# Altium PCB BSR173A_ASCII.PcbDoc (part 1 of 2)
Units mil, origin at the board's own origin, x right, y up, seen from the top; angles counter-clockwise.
Board outline 3000 x 1500 mil, 4 copper layers (Top Layer, Signal Layer 1, Signal Layer 2, Bottom Layer), stack 61.2 mil thick; 64 components, 17 nets, 119 pads, 82 vias.
Unrouted connection lines stored in the file: 2.
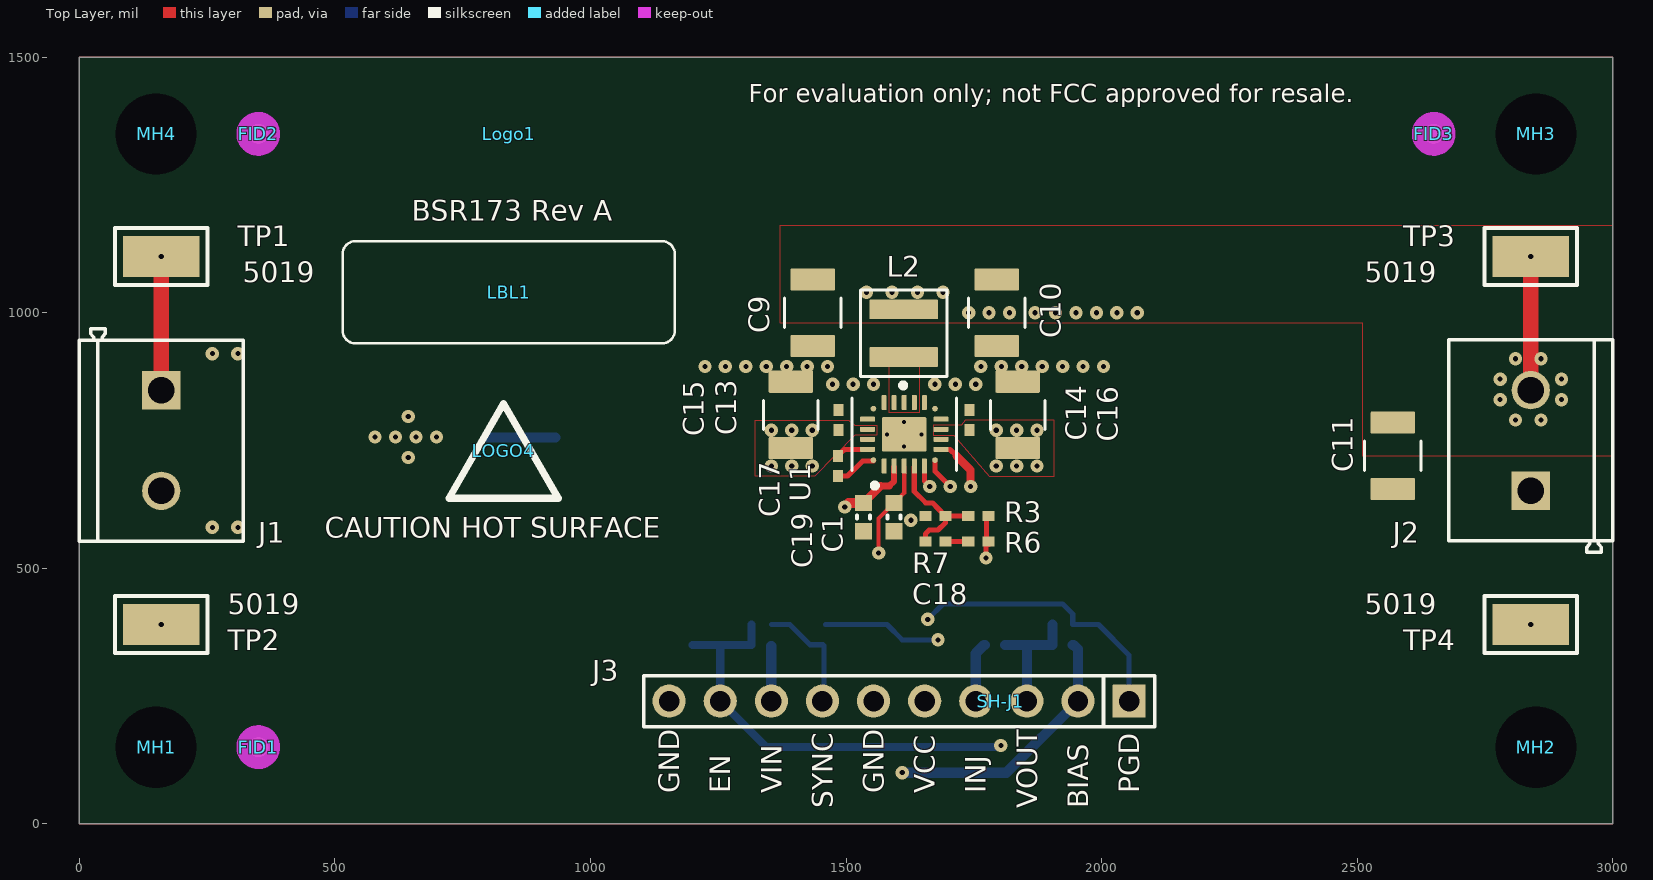
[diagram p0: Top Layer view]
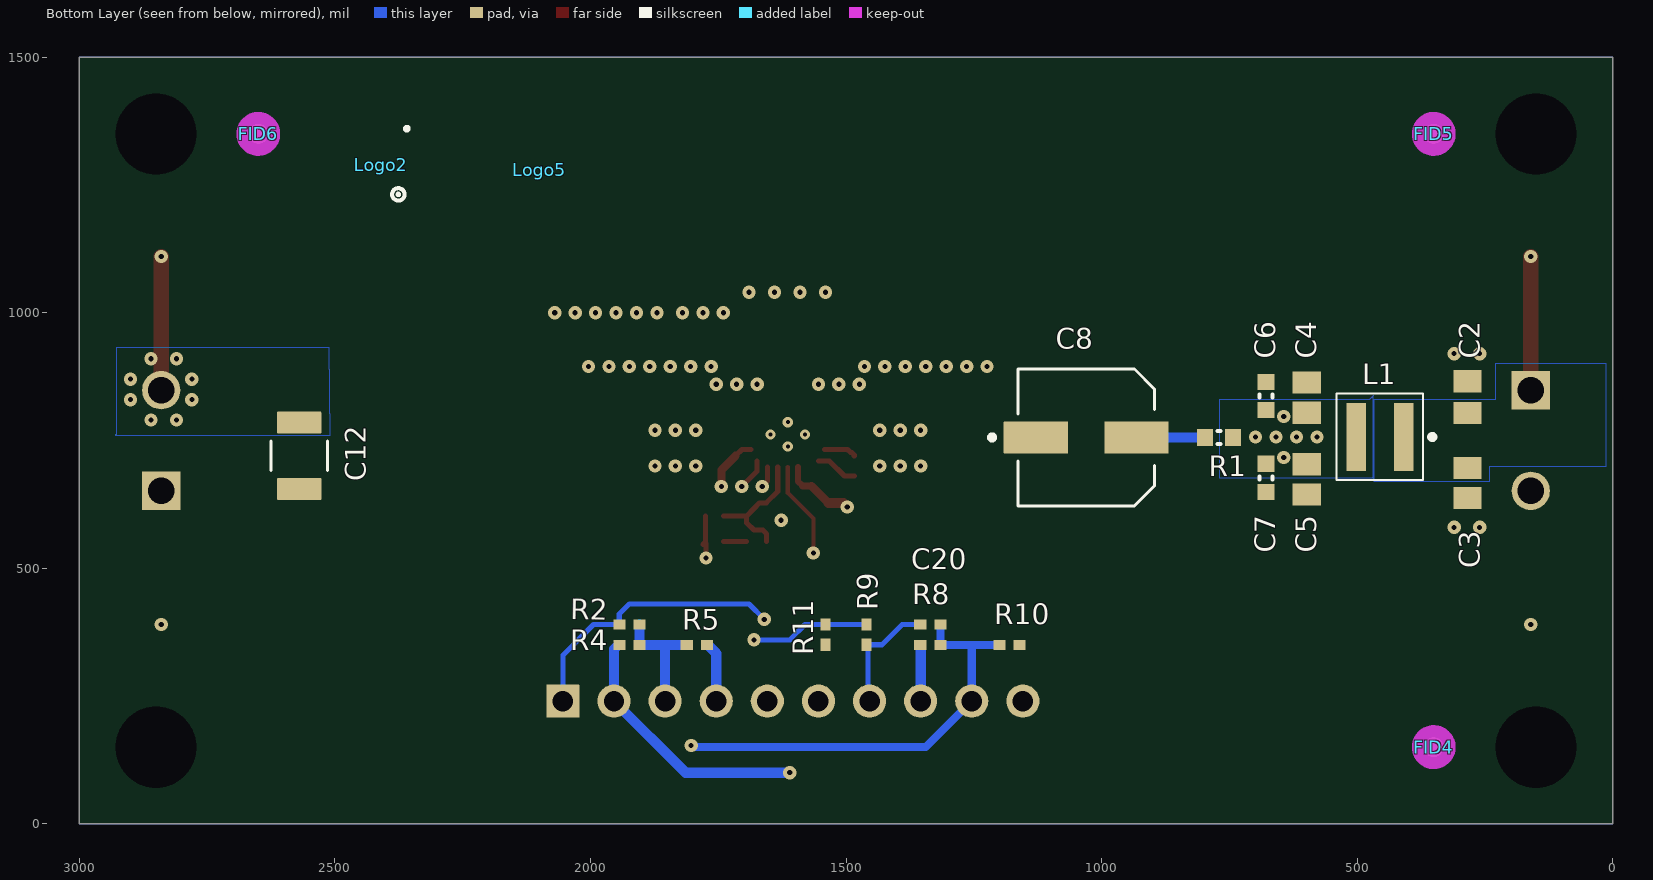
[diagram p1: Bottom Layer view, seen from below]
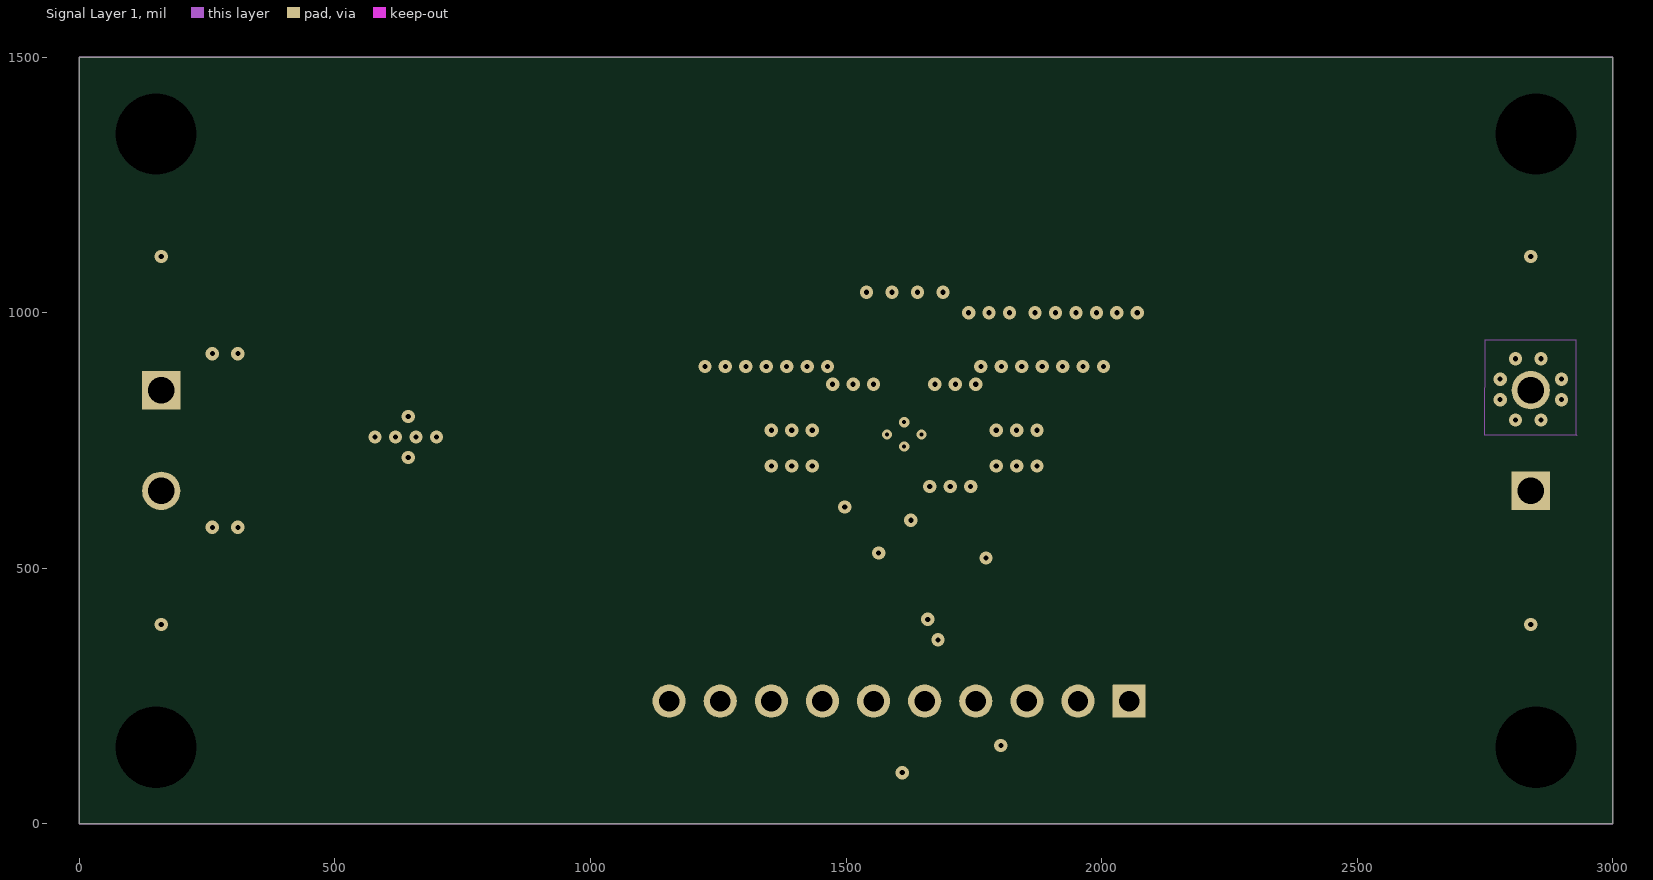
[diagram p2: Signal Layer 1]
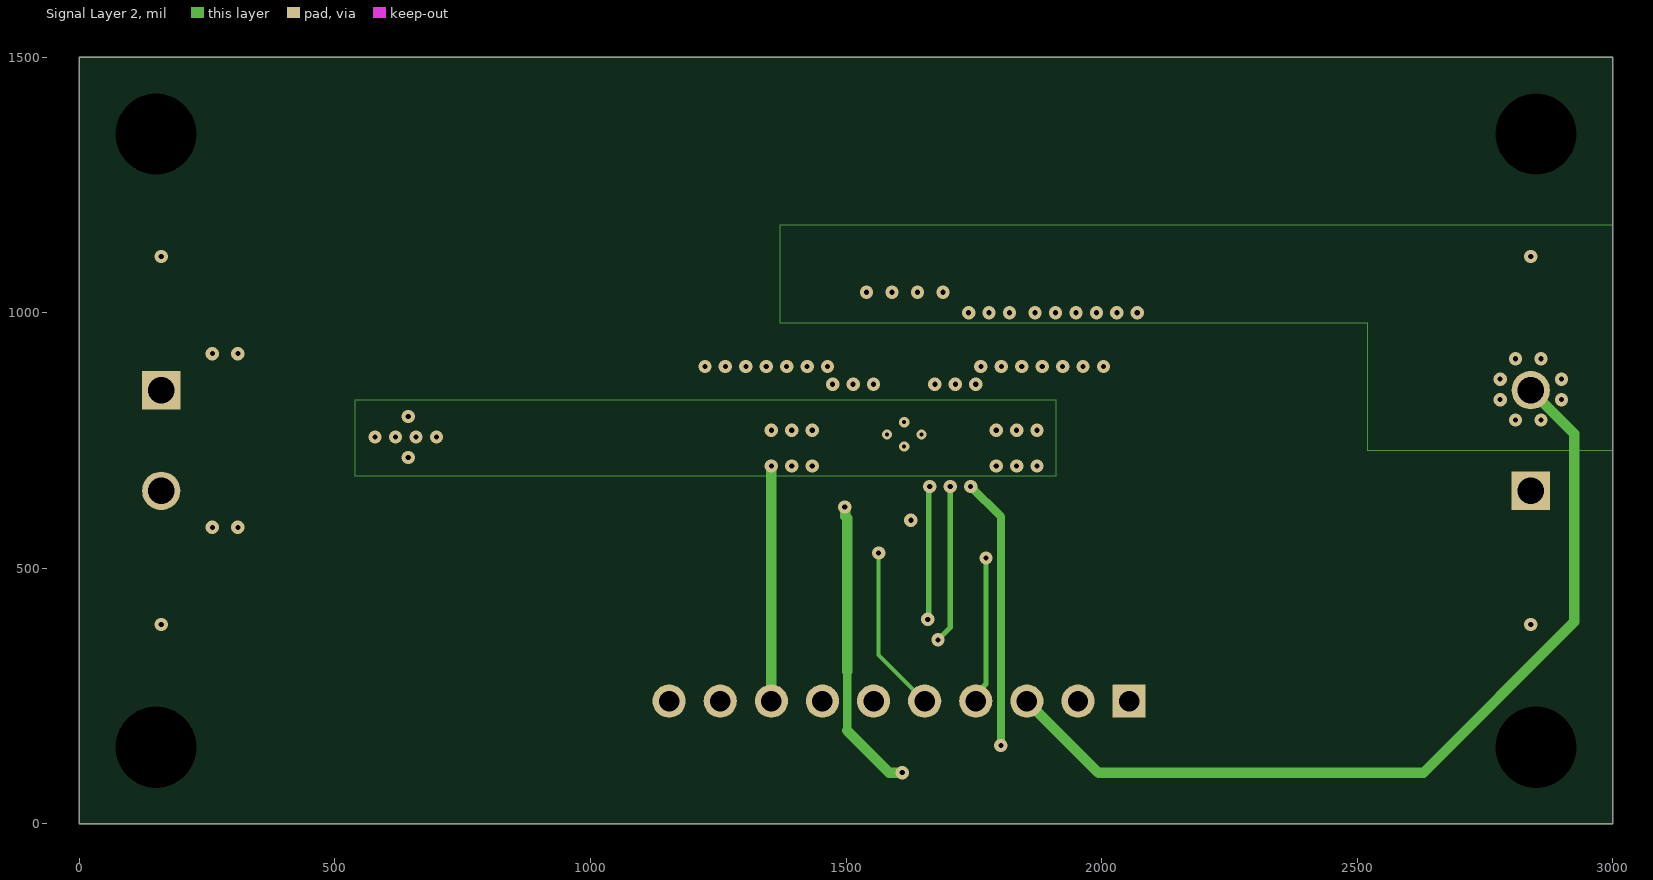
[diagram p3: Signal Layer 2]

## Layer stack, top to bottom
Top Solder: solder mask 0.4, Solder Resist, Dk 3.5
Top Layer: signal copper 2.8
Dielectric 1: prepreg 5, FR-4 High Tg, Dk 4.2
Signal Layer 1: signal copper 2.8
Dielectric 2: core 40, FR-4 High Tg, Dk 4.2
Signal Layer 2: signal copper 2.8
Dielectric 3: prepreg 5, FR-4 High Tg, Dk 4.2
Bottom Layer: signal copper 2.8
Bottom Solder: solder mask 0.4, Solder Resist, Dk 3.5

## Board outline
0,0 0,1500 3000,1500 3000,0

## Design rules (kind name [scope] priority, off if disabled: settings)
AcuteAngle [All] p0: scope1count=1 scope1_0_kind=Board scope1_0_value=Board scope2count=1 scope2_0_kind=Board scope2_0_value=Board commentlength=0 minimum=4.50000000000000E+0001
AcuteAngle [All] p1: minimum=4.50000000000000E+0001 checktracksonly=FALSE
AssemblyTestPointUsage [All] p0: scope1count=1 scope1_0_kind=Board scope1_0_value=Board scope2count=1 scope2_0_kind=Board scope2_0_value=Board commentlength=0
AssemblyTestPointUsage [All] p1: valid=2
AssemblyTestpoint [All] p0: scope1count=1 scope1_0_kind=Board scope1_0_value=Board scope2count=1 scope2_0_kind=Board scope2_0_value=Board commentlength=0
BoardOutlineClearance BoardOutlineClearance_MountingHoles [All] p0 off: scope1count=1 scope1_0_kind=Board scope1_0_value=Board scope2count=1 scope2_0_kind=Board scope2_0_value=Board commentlength=86 gap=40 // Protel DXP Scope 1 Expression Was: OnCopper and InComponentClass('Mounting Holes')
BoardOutlineClearance BoardOutlineClearance_Poly [All] p0 off: scope1count=1 scope1_0_kind=Board scope1_0_value=Board scope2count=1 scope2_0_kind=Board scope2_0_value=Board commentlength=58 gap=25 // Protel DXP Scope 1 Expression Was: OnCopper and IsPoly
BoardOutlineClearance [All] p0 off: scope1count=1 scope1_0_kind=Board scope1_0_value=Board scope2count=1 scope2_0_kind=Board scope2_0_value=Board commentlength=172 gap=65 // Protel DXP Scope 1 Expression Was: OnCopper and Not InComponentClass('Logo') and not InComponentClass('FiducialMark') and not InRegion(1000,500,4000,800) and not InPoly
BoardOutlineClearance BoardOutlineClearance_1 [All] p0: scope1count=1 scope1_0_kind=Footprint scope1_0_value=Edge_Connector_EDAC_12x2 scope2count=1 scope2_0_kind=Board scope2_0_value=Board commentlength=0 gap=0
BoardOutlineClearance BoardOutlineClearance_1 [HasFootprint('Edge_Connector_EDAC_12x2')] p1: gap=0 ignorepadtopadclearanceinfootprint=FALSE
BoardOutlineClearance BoardOutlineClearance_MountingHoles [OnCopper and InComponentClass('Mounting Holes')] p2: gap=40 ignorepadtopadclearanceinfootprint=FALSE
BoardOutlineClearance BoardOutlineClearance_Poly [OnCopper and IsPoly] p3: gap=25 ignorepadtopadclearanceinfootprint=FALSE
BoardOutlineClearance [OnCopper and Not InComponentClass('Logo') and not InComponentClass('FiducialMark') and not InRegion(1000,500,4000,800) and not InPoly] p4: gap=65 ignorepadtopadclearanceinfootprint=FALSE
Clearance "Stitching VIN_PIN" [All] p0 off: scope1count=1 scope1_0_kind=Board scope1_0_value=Board scope2count=1 scope2_0_kind=Board scope2_0_value=Board commentlength=80 gap=9 // Protel DXP Scope 2 Expression Was: (IsVia and (Not IsStitchingVia)) Or IsPad
Clearance Clearance_Keepouts [All] p0 off: scope1count=1 scope1_0_kind=Board scope1_0_value=Board scope2count=1 scope2_0_kind=Board scope2_0_value=Board commentlength=99 gap=0 // Protel DXP Scope 2 Expression Was: ((IsTrack Or IsArc) And Not InPoly) And IsFree and IsKeepOut
Clearance Clearance_Poly [All] p0 off: scope1count=1 scope1_0_kind=Board scope1_0_value=Board scope2count=1 scope2_0_kind=Board scope2_0_value=Board commentlength=48 gap=10 // Protel DXP Scope 1 Expression Was: InPolygon
Clearance Clearance_FiducialMark [All] p0 off: scope1count=1 scope1_0_kind=Board scope1_0_value=Board scope2count=1 scope2_0_kind=Board scope2_0_value=Board commentlength=81 gap=0 // Protel DXP Scope 2 Expression Was: IsPad and InComponentClass('FiducialMark')
Clearance [All] p0: scope1count=1 scope1_0_kind=Board scope1_0_value=Board scope2count=1 scope2_0_kind=Board scope2_0_value=Board commentlength=0 gap=7.87
Clearance "Stitching VIN_PIN" [IsStitchingVia and InNet('VIN_PIN') vs (IsVia and (Not IsStitchingVia)) Or IsPad] p1: gap=9 ignorepadtopadclearanceinfootprint=FALSE
Clearance Clearance_Keepouts [((IsTrack Or IsArc) And Not InPoly) And IsFree and IsKeepOut vs ((IsTrack Or IsArc) And Not InPoly) And IsFree and IsKeepOut] p2: gap=0 ignorepadtopadclearanceinfootprint=FALSE
Clearance Clearance_Poly [InPolygon] p3: gap=10 ignorepadtopadclearanceinfootprint=FALSE
Clearance Clearance_FiducialMark [IsKeepOut and InComponentClass('FiducialMark') vs IsPad and InComponentClass('FiducialMark')] p4: gap=0 ignorepadtopadclearanceinfootprint=FALSE
Clearance [All] p5: gap=7.87 ignorepadtopadclearanceinfootprint=FALSE except(0: Arc-Hole Track-Hole SMDPad-Hole THPad-Hole Via-Hole Fill-Hole Poly-Hole Region-Hole Text-Hole)
ComponentClearance ComponentClearance_MountingHoles_FiducialMarks [All] p0: scope1count=1 scope1_0_kind=ComponentClass scope1_0_value="Mounting Holes" scope2count=1 scope2_0_kind=ComponentClass scope2_0_value=FiducialMark commentlength=0 gap=50 collisioncheckmode=3
ComponentClearance ComponentClearance_Shunt [All] p0: scope1count=1 scope1_0_kind=ComponentClass scope1_0_value=Header scope2count=1 scope2_0_kind=ComponentClass scope2_0_value=Shunt commentlength=0 gap=0 collisioncheckmode=3
ComponentClearance ComponentClearance_Logo [All] p0: scope1count=1 scope1_0_kind=ComponentClass scope1_0_value=Logo scope2count=1 scope2_0_kind=Board scope2_0_value=Board commentlength=0 gap=50 collisioncheckmode=3
ComponentClearance ComponentClearance_ScrewToNut [All] p0 off: scope1count=1 scope1_0_kind=Board scope1_0_value=Board scope2count=1 scope2_0_kind=Board scope2_0_value=Board commentlength=71 gap=5 collisioncheckmode=3 // Protel DXP Scope 2 Expression Was: (HasFootprint('Keystone_1902C'))
ComponentClearance ComponentClearance_MountingHoles [All] p0: scope1count=1 scope1_0_kind=ComponentClass scope1_0_value="Mounting Holes" scope2count=1 scope2_0_kind=Board scope2_0_value=Board commentlength=0 gap=0 collisioncheckmode=3
ComponentClearance ComponentClearance_SmallPassives [All] p0 off: scope1count=1 scope1_0_kind=Board scope1_0_value=Board scope2count=1 scope2_0_kind=Board scope2_0_value=Board commentlength=508 gap=14.96 collisioncheckmode=3 // Protel DXP Scope 2 Expression Was: HasFootprint('0201*') or HasFootprint('0402*') or HasFootprint('0508') or HasFootprint('0603*') or HasFootprint('0612') or HasFootprint('0805*') or HasFootprint('0815*') or HasFootprint('0830*') or HasFootprint('1206*') or HasFootprint('1210*') or HasFootprint('1808*') or HasFootprint('1812*') or HasFootprint('1825*') or HasFootprint('2010*') or HasFootprint('2220*') or HasFootprint('2225*') or HasFootprint('2512*') or HasFootprint('2728*') or HasFootprint('3518*')
ComponentClearance ComponentClearance_THtoSMT [All] p0 off: scope1count=1 scope1_0_kind=Board scope1_0_value=Board scope2count=1 scope2_0_kind=Board scope2_0_value=Board commentlength=53 gap=40 collisioncheckmode=3 // Protel DXP Scope 2 Expression Was: IsSMTComponent
ComponentClearance ComponentClearance_THtoTH [All] p0 off: scope1count=1 scope1_0_kind=Board scope1_0_value=Board scope2count=1 scope2_0_kind=Board scope2_0_value=Board commentlength=54 gap=30 collisioncheckmode=3 // Protel DXP Scope 2 Expression Was: IsThruComponent
ComponentClearance [All] p0: scope1count=1 scope1_0_kind=Board scope1_0_value=Board scope2count=1 scope2_0_kind=Board scope2_0_value=Board commentlength=0 gap=30 collisioncheckmode=3
ComponentClearance ComponentClearance_MountingHoles_FiducialMarks [InComponentClass('Mounting Holes') vs InComponentClass('FiducialMark')] p1: gap=50 collisioncheckmode=3 verticalgap=10 showdistances=FALSE
ComponentClearance ComponentClearance_Shunt [InComponentClass('Header') vs InComponentClass('Shunt')] p2: gap=0 collisioncheckmode=3 verticalgap=0 showdistances=FALSE
ComponentClearance ComponentClearance_Logo [InComponentClass('Logo')] p3: gap=50 collisioncheckmode=3 verticalgap=10 showdistances=FALSE
ComponentClearance ComponentClearance_ScrewToNut [(HasFootprint('NY PMS 440 0025 PH')) vs (HasFootprint('Keystone_1902C'))] p4: gap=5 collisioncheckmode=3 verticalgap=10 showdistances=FALSE
ComponentClearance ComponentClearance_MountingHoles [InComponentClass('Mounting Holes')] p5: gap=0 collisioncheckmode=3 verticalgap=100000 showdistances=FALSE
ComponentClearance ComponentClearance_SmallPassives [HasFootprint('0201*') or HasFootprint('0402*') or HasFootprint('0508') or HasFootprint('0603*') or HasFootprint('0612') or HasFootprint('0805*') or HasFootprint('0815*') or HasFootprint('0830*') or HasFootprint('1206*') or HasFootprint('1210*') or HasFootprint('1808*') or HasFootprint('1812*') or HasFootprint('1825*') or HasFootprint('2010*') or HasFootprint('2220*') or HasFootprint('2225*') or HasFootprint('2512*') or HasFootprint('2728*') or HasFootprint('3518*') vs HasFootprint('0201*') or HasFootprint('0402*') or HasFootprint('0508') or HasFootprint('0603*') or HasFootprint('0612') or HasFootprint('0805*') or HasFootprint('0815*') or HasFootprint('0830*') or HasFootprint('1206*') or HasFootprint('1210*') or HasFootprint('1808*') or HasFootprint('1812*') or HasFootprint('1825*') or HasFootprint('2010*') or HasFootprint('2220*') or HasFootprint('2225*') or HasFootprint('2512*') or HasFootprint('2728*') or HasFootprint('3518*')] p6: gap=14.96 collisioncheckmode=3 verticalgap=10 showdistances=FALSE
ComponentClearance ComponentClearance_THtoSMT [IsThruComponent vs IsSMTComponent] p7: gap=40 collisioncheckmode=3 verticalgap=30 showdistances=FALSE
ComponentClearance ComponentClearance_THtoTH [IsThruComponent vs IsThruComponent] p8: gap=30 collisioncheckmode=3 verticalgap=30 showdistances=FALSE
ComponentClearance [All] p9: gap=30 collisioncheckmode=3 verticalgap=10 showdistances=FALSE
DiffPairsRouting [All] p0: scope1count=1 scope1_0_kind=Board scope1_0_value=Board scope2count=1 scope2_0_kind=Board scope2_0_value=Board commentlength=0
DiffPairsRouting [All] p1: maxlimit=100 minlimit=10 mostfreqgap=10 toplayer_minwidth=15 toplayer_maxwidth=15 toplayer_prefwidth=15 midlayer1_minwidth=15 midlayer1_maxwidth=15 midlayer1_prefwidth=15 midlayer2_minwidth=15 midlayer2_maxwidth=15 midlayer2_prefwidth=15 bottomlayer_minwidth=15 bottomlayer_maxwidth=15 bottomlayer_prefwidth=15 maxuncoupledlength=1000
FabricationTestPointUsage TestPointUsage [All] p0: scope1count=1 scope1_0_kind=Board scope1_0_value=Board scope2count=1 scope2_0_kind=Board scope2_0_value=Board commentlength=0 valid=2 allowmultiple=FALSE
FabricationTestPointUsage TestPointUsage [All] p1: valid=2 allowmultiple=FALSE
FabricationTestpoint Testpoint [All] p0: scope1count=1 scope1_0_kind=Board scope1_0_value=Board scope2count=1 scope2_0_kind=Board scope2_0_value=Board commentlength=0 side=3 testpointundercomponent=TRUE minsize=40 maxsize=100 preferedsize=60 minholesize=0 maxholesize=40 preferedholesize=32 testpointgrid=1
FabricationTestpoint Testpoint [All] p1: side=3 testpointundercomponent=TRUE minsize=40 maxsize=100 preferedsize=60 minholesize=0 maxholesize=40 preferedholesize=32 testpointgrid=1 allowsidetop=TRUE allowsidebottom=TRUE usegrid=TRUE gridtolerance=0.01
FanoutControl Fanout_LCC [All] p0 off: scope1count=1 scope1_0_kind=Board scope1_0_value=Board scope2count=1 scope2_0_kind=Board scope2_0_value=Board commentlength=69 // Protel DXP Scope 1 Expression Was: IsLCC   Fanout_LCC (Default Rule)
FanoutControl Fanout_BGA [All] p0 off: scope1count=1 scope1_0_kind=Board scope1_0_value=Board scope2count=1 scope2_0_kind=Board scope2_0_value=Board commentlength=69 // Protel DXP Scope 1 Expression Was: IsBGA   Fanout_BGA (Default Rule)
FanoutControl Fanout_SOIC [All] p0 off: scope1count=1 scope1_0_kind=Board scope1_0_value=Board scope2count=1 scope2_0_kind=Board scope2_0_value=Board commentlength=71 // Protel DXP Scope 1 Expression Was: IsSOIC   Fanout_SOIC (Default Rule)
FanoutControl Fanout_Default [All] p0: scope1count=1 scope1_0_kind=Board scope1_0_value=Board scope2count=1 scope2_0_kind=Board scope2_0_value=Board commentlength=30 // Fanout_Default (Default Rule)
FanoutControl Fanout_Small [All] p0 off: scope1count=1 scope1_0_kind=Board scope1_0_value=Board scope2count=1 scope2_0_kind=Board scope2_0_value=Board commentlength=84 // Protel DXP Scope 1 Expression Was: (CompPinCount < 5)   Fanout_Small (Default Rule)
FanoutControl Fanout_LCC [IsLCC] p1: bgadir=Out bgaviamode=Centered fanoutstyle=Auto fanoutdirection=Alternating viagrid=1 // Fanout_LCC (Default Rule)
FanoutControl Fanout_BGA [IsBGA] p2: bgadir=Out bgaviamode=Centered fanoutstyle=Auto fanoutdirection=Alternating viagrid=1 // Fanout_BGA (Default Rule)
FanoutControl Fanout_Default [All] p4: bgadir=Out bgaviamode=Centered fanoutstyle=Auto fanoutdirection=Alternating viagrid=1 // Fanout_Default (Default Rule)
FanoutControl Fanout_Small [(CompPinCount < 5)] p5: bgadir=Out bgaviamode=Centered fanoutstyle=Auto fanoutdirection=OutThenIn viagrid=1 // Fanout_Small (Default Rule)
Height [All] p0: scope1count=1 scope1_0_kind=Board scope1_0_value=Board scope2count=1 scope2_0_kind=Board scope2_0_value=Board commentlength=0
HoleSize [All] p0: scope1count=1 scope1_0_kind=Board scope1_0_value=Board scope2count=1 scope2_0_kind=Board scope2_0_value=Board commentlength=0 absolutevalues=TRUE maxlimit=251 minlimit=7.87 maxpercent=80.000 minpercent=20.000
HoleSize [All] p1: absolutevalues=TRUE maxlimit=251 minlimit=7.87 maxpercent=80.000 minpercent=20.000
HoleToHoleClearance [All] p0: scope1count=1 scope1_0_kind=Board scope1_0_value=Board scope2count=1 scope2_0_kind=Board scope2_0_value=Board commentlength=0
LayerPairs [All] p0: scope1count=1 scope1_0_kind=Board scope1_0_value=Board scope2count=1 scope2_0_kind=Board scope2_0_value=Board commentlength=0 enforce=TRUE
MinimumAnnularRing MinimumAnnularRing_ThermalPadVias [All] p0 off: scope1count=1 scope1_0_kind=Board scope1_0_value=Board scope2count=1 scope2_0_kind=Board scope2_0_value=Board commentlength=63 minimumring=5.91 // Protel DXP Scope 1 Expression Was: IsVia and InAnyComponent
MinimumAnnularRing [All] p0: scope1count=1 scope1_0_kind=Board scope1_0_value=Board scope2count=1 scope2_0_kind=Board scope2_0_value=Board commentlength=0 minimumring=7
MinimumAnnularRing MinimumAnnularRing_ThermalPadVias [IsVia and InAnyComponent] p1: minimumring=5.91
MinimumAnnularRing [All] p2: minimumring=7
MinimumSolderMaskSliver MinimumSolderMaskSliver_Logo [All] p0: scope1count=1 scope1_0_kind=ComponentClass scope1_0_value=Logo scope2count=1 scope2_0_kind=ComponentClass scope2_0_value=Logo commentlength=0
MinimumSolderMaskSliver [All] p0: scope1count=1 scope1_0_kind=Board scope1_0_value=Board scope2count=1 scope2_0_kind=Board scope2_0_value=Board commentlength=0
MinimumSolderMaskSliver MinimumSolderMaskSliver_Logo [InComponentClass('Logo') vs InComponentClass('Logo')] p1: minsoldermaskwidth=0.7
MinimumSolderMaskSliver [All] p2: minsoldermaskwidth=3.94
NetAntennae [All] p0: scope1count=1 scope1_0_kind=Board scope1_0_value=Board scope2count=1 scope2_0_kind=Board scope2_0_value=Board commentlength=0
PasteMaskExpansion [All] p0: scope1count=1 scope1_0_kind=Board scope1_0_value=Board scope2count=1 scope2_0_kind=Board scope2_0_value=Board commentlength=0 expansion=0
PlaneClearance [All] p0: scope1count=1 scope1_0_kind=Board scope1_0_value=Board scope2count=1 scope2_0_kind=Board scope2_0_value=Board commentlength=0 clearance=20
PlaneConnect [All] p0: scope1count=1 scope1_0_kind=Board scope1_0_value=Board scope2count=1 scope2_0_kind=Board scope2_0_value=Board commentlength=0 planeconnectstyle=Direct reliefexpansion=10 reliefentries=4 reliefconductorwidth=10 reliefairgap=10
PlaneConnect [All] p1: planeconnectstyle=Direct reliefexpansion=10 reliefentries=4 reliefconductorwidth=10 reliefairgap=10
PolygonConnect [All] p0: scope1count=1 scope1_0_kind=Board scope1_0_value=Board scope2count=1 scope2_0_kind=Board scope2_0_value=Board commentlength=0 connectstyle=Direct reliefconductorwidth=10 reliefentries=4 polygonreliefangle="90 Angle"
PolygonConnect [All] p1: connectstyle=Direct reliefconductorwidth=10 reliefentries=4 polygonreliefangle="90 Angle" airgapwidth=10
RoutingCorners [All] p0: scope1count=1 scope1_0_kind=Board scope1_0_value=Board scope2count=1 scope2_0_kind=Board scope2_0_value=Board commentlength=0 cornerstyle=45-Degree minsetback=100 maxsetback=100
RoutingLayers [All] p0: scope1count=1 scope1_0_kind=Board scope1_0_value=Board scope2count=1 scope2_0_kind=Board scope2_0_value=Board commentlength=0 top layer=Automatic mid layer 1=Automatic mid layer 2=Automatic bottom layer=Automatic
RoutingPriority [All] p0: scope1count=1 scope1_0_kind=Board scope1_0_value=Board scope2count=1 scope2_0_kind=Board scope2_0_value=Board commentlength=0
RoutingTopology [All] p0: scope1count=1 scope1_0_kind=Board scope1_0_value=Board scope2count=1 scope2_0_kind=Board scope2_0_value=Board commentlength=0 topology=Shortest
RoutingVias ThermalPadVias [All] p0 off: scope1count=1 scope1_0_kind=Board scope1_0_value=Board scope2count=1 scope2_0_kind=Board scope2_0_value=Board commentlength=63 holewidth=7.87 width=19.68 viastyle="Through Hole" minholewidth=7.87 minwidth=19.68 maxholewidth=12.99 maxwidth=23.62 // Protel DXP Scope 1 Expression Was: IsVia and InAnyComponent
RoutingVias [All] p0: scope1count=1 scope1_0_kind=Board scope1_0_value=Board scope2count=1 scope2_0_kind=Board scope2_0_value=Board commentlength=0 holewidth=16 width=34 viastyle="Through Hole" minholewidth=7.87 minwidth=20 maxholewidth=40 maxwidth=65
RoutingVias ThermalPadVias [IsVia and InAnyComponent] p1: holewidth=7.87 width=19.68 viastyle="Through Hole" minholewidth=7.87 minwidth=19.68 maxholewidth=12.99 maxwidth=23.62
RoutingVias [All] p2: holewidth=16 width=34 viastyle="Through Hole" minholewidth=7.87 minwidth=20 maxholewidth=40 maxwidth=65
ShortCircuit [All] p0: scope1count=1 scope1_0_kind=Board scope1_0_value=Board scope2count=1 scope2_0_kind=Board scope2_0_value=Board commentlength=0 allowed=FALSE
SilkToBoardRegionClearance [All] p0 off: scope1count=1 scope1_0_kind=Board scope1_0_value=Board scope2count=1 scope2_0_kind=Board scope2_0_value=Board commentlength=130 // Protel DXP Scope 1 Expression Was: Not ((IsComment or IsDesignator) And (Hide <> 'False')) and not InRegion(1000,500,4000,800)
SilkToBoardRegionClearance [Not ((IsComment or IsDesignator) And (Hide <> 'False')) and not InRegion(1000,500,4000,800)] p1:
SilkToSilkClearance SilkToSilkClearance_Pb-FreeLogo [All] p0 off: scope1count=1 scope1_0_kind=Board scope1_0_value=Board scope2count=1 scope2_0_kind=Board scope2_0_value=Board commentlength=120 // Protel DXP Scope 2 Expression Was: (HasFootprint('Pb-Free_Overlay_Medium') OR HasFootprint('Pb-Free_Overlay_Small'))
SilkToSilkClearance [All] p0: scope1count=1 scope1_0_kind=Board scope1_0_value=Board scope2count=1 scope2_0_kind=Board scope2_0_value=Board commentlength=0
SilkToSilkClearance SilkToSilkClearance_Pb-FreeLogo [(HasFootprint('Pb-Free_Overlay_Medium') OR HasFootprint('Pb-Free_Overlay_Small')) vs (HasFootprint('Pb-Free_Overlay_Medium') OR HasFootprint('Pb-Free_Overlay_Small'))] p1: silktosilkclearance=0
SilkToSilkClearance [All] p2: silktosilkclearance=4
SilkToSolderMaskClearance SilkToComponentPadClearance [All] p0 off: scope1count=1 scope1_0_kind=Board scope1_0_value=Board scope2count=1 scope2_0_kind=Board scope2_0_value=Board commentlength=87 // Protel DXP Scope 1 Expression Was: (IsPad or IsFill or IsRegion) and InAnycomponent
SilkToSolderMaskClearance "Silk to Solder Mask Opening" [All] p0: scope1count=1 scope1_0_kind=Board scope1_0_value=Board scope2count=1 scope2_0_kind=Board scope2_0_value=Board commentlength=0
SilkToSolderMaskClearance SilkToComponentPadClearance [(IsPad or IsFill or IsRegion) and InAnycomponent] p1: minsilkscreentomaskgap=5 clearancetoexposedcopper=TRUE
SilkToSolderMaskClearance "Silk to Solder Mask Opening" [All] p2: minsilkscreentomaskgap=4 clearancetoexposedcopper=FALSE
SolderMaskExpansion [All] p0: scope1count=1 scope1_0_kind=Board scope1_0_value=Board scope2count=1 scope2_0_kind=Board scope2_0_value=Board commentlength=0 expansion=1.97
SolderMaskExpansion [All] p1: expansion=1.97 istentingtop=FALSE
UnRoutedNet [All] p0: scope1count=1 scope1_0_kind=Board scope1_0_value=Board scope2count=1 scope2_0_kind=Board scope2_0_value=Board commentlength=0
UnpouredPolygon [All] p0: scope1count=1 scope1_0_kind=Board scope1_0_value=Board scope2count=1 scope2_0_kind=Board scope2_0_value=Board commentlength=0
Width [All] p0: scope1count=1 scope1_0_kind=Board scope1_0_value=Board scope2count=1 scope2_0_kind=Board scope2_0_value=Board commentlength=0 maxlimit=200 minlimit=6 preferedwidth=10
Width [All] p1: maxlimit=200 minlimit=6 preferedwidth=10 checkconnectedcopper=TRUE
15 further rules are at their usual default settings.

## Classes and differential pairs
component class Shunt: SH-J1
component class Label: LBL1
component class Header: J3
component class BSR173A: C1 C2 C3 C4 C5 C6 C7 C8 C9 C10 C11 C12 C13 C14 C15 C16 C17 C18 C19 C20 C23 D1 J1 J2 J3 J7 L1 L2 L-FLT L? PL1 R1 R2 R3 R4 R5 R6 R7 R8 R9 R10 R11 R13 R14 R15 R? TP1 TP2 TP3 TP4 TP11 TP13 TP17 TP? U1
component class Logo: Logo1
component class AssemblyNote: ZZ1 ZZ2 ZZ3 ZZ4 ZZ5 ZZ6
component class BSR173A_Hardware: !PCB FID1 FID2 FID3 FID4 FID5 FID6 LBL1 Logo1 Logo2 Logo3 LOGO4 Logo4 Logo5 Logo10 MH1 MH2 MH3 MH4 SH-J1 ZZ1 ZZ2 ZZ3 ZZ4 ZZ5 ZZ6
component class FiducialMark: FID1 FID2 FID3 FID4 FID5 FID6

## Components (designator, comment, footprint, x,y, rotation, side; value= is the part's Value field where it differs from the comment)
C1 "C0603C105K4RACAUTO" 0603L 1593.94,600 r270 top
C2 "CGA4J3X7R1H225K125AB" 0805L#1 283.58,833 r90 bottom
C3 "CGA4J3X7R1H225K125AB" 0805L#2 283.58,667 r270 bottom
C4 "CGA4J3X7R1H225K125AB" 0805L#2 598.5,833.9 r90 bottom
C5 "CGA4J3X7R1H225K125AB" 0805L#2 598.5,673.9 r270 bottom
C6 "CGA3E3X7R1H474K080AE" 0603L 678.5,836.9 r90 bottom
C7 "CGA3E3X7R1H474K080AE" 0603L 678.5,676.9 r270 bottom
C8 "EEE-FN1H680XL" FP-EEE-FN1H680XL_RADIAL-MFG 1030,756 r180 bottom
C9 "CGA6P1X7S1A476M250AC" FP-CGA6P1X7S1A476M250AC_1210-MFG 1435,1000 r270 top
C10 "CGA6P1X7S1A476M250AC" FP-CGA6P1X7S1A476M250AC_1210-MFG 1795,1000 r270 top
C11 "CGA6P1X7S1A476M250AC" FP-CGA6P1X7S1A476M250AC_1210-MFG 2570,720 r270 top
C12 "CGA6P1X7S1A476M250AC" FP-CGA6P1X7S1A476M250AC_1210-MFG 2570,720 r270 bottom
C13 "GRM155R71H223KA12D" 0402L 1485,790 r90 top
C14 "GRM155R71H223KA12D" 0402L 1742,790 r90 top
C15 "CNA6P1X7R1H106K250AE" FP-CNA6P1X7R1H106K250AE_1210-MFG 1392,800 r90 top
C16 "CNA6P1X7R1H106K250AE" FP-CNA6P1X7R1H106K250AE_1210-MFG 1836,800 r90 top
C17 "C0402C104K8RACTU" 0402L 1483.94,700 r270 top
C18 "CGA2B2NP01H220J050BA" 0402L 1675.16,552 r0 top
C19 "C0603C105K4RACAUTO" 0603L 1533.94,600 r90 top
C20 "CGA2B2X7R1H102K050BA" 0402L 1335,390 r180 bottom
FID1 "Fiducial" Fiducial10-20 350,150 r0 top
FID2 "Fiducial" Fiducial10-20 350,1350 r0 top
FID3 "Fiducial" Fiducial10-20 2650,1350 r0 top
FID4 "Fiducial" Fiducial10-20 350,150 r180 bottom
FID5 "Fiducial" Fiducial10-20 350,1350 r180 bottom
FID6 "Fiducial" Fiducial10-20 2650,1350 r180 bottom
J1 "1729018" Phoenix_1729018 160,750 r270 top
J2 "1729018" Phoenix_1729018 2840,750 r90 top
J3 "TSW-110-07-G-S" TSW-110-07-G-S 1603.94,240 r180 top
L1 "XGL4020-102MEC" FP-XGL4020-102MEC_SMT_IND_4MM0_4MM0-MFG 455.16,756.9 r0 bottom
L2 "XGL4030-761MEC" FP-XGL4030-761MEC_SMD_IND_4MM0_4MM0-MFG 1613,960 r90 top
LBL1 "THT-14-423-10" Label_650x200 840,1040 r180 top
Logo1 "Texas Instruments" TI_Stacked_Overlay_Small 840,1350 r0 top
Logo2 "WEEE logo" WEEE_Minimum 2410,1290 r180 bottom
Logo3 "FCC disclaimer" FCC_disclaimer 7341.5,-892 r90 top
LOGO4 "CAUTION HOT SURFACE" IEC_HotSurface_Small 830,730 r0 top
Logo5 "CE Mark" CE_Mark_5mm 2100,1280 r180 bottom (schematic designator LOGO5)
MH1 "MTG_NoPads" MTG_159mil 150,150 r0 top
MH2 "MTG_NoPads" MTG_159mil 2850,150 r0 top
MH3 "MTG_NoPads" MTG_159mil 2850,1350 r0 top
MH4 "MTG_NoPads" MTG_159mil 150,1350 r0 top
R1 "CRCW06030000Z0EA" 0603L 770,756 r180 bottom
R2 "CRCW0402100KFKED" 0402L 1923.94,390 r180 bottom
R3 "CRCW0402100KFKED" 0402L 1758.94,602 r0 top
R4 "CRCW04021R00FKED" 0402L 1923.94,350 r0 bottom
R5 "CRCW040249R9FKED" 0402L 1791.94,350 r180 bottom
R6 "CRCW04021K00FKED" 0402L 1758.94,552 r180 top
R7 "CRCW040224K9FKED" 0402L 1674.84,602 r180 top
R8 "CRCW0402255KFKED" 0402L 1335,350 r0 bottom
R9 "CRCW04020000Z0ED" 0402L 1460,370 r270 bottom
R10 "CRCW0402100KFKED" 0402L 1180,350 r180 bottom
R11 "CRCW0402100KFKED" 0402L 1540,370 r270 bottom
SH-J1 "SNT-100-BK-G" SNT-100-BK-G 1803,240 r180 top
TP1 "5019" Keystone_5019 160,1110 r180 top
TP2 "5019" Keystone_5019 160,390 r0 top
TP3 "5019" Keystone_5019 2840,1110 r180 top
TP4 "5019" Keystone_5019 2840,390 r180 top
U1 "LM64460APPQRYFRQ1" RYF0022A-MFG 1613.94,762.13 r90 top
ZZ1 "This Assembly Note is for PCB labels only" AssemblyNoteLabel 200,2620 r0 top
ZZ2 "These assemblies are ESD sensitive, ESD precautions shall be observed." AssemblyNote 190,2500 r0 top
ZZ3 "These assemblies must be clean and free from flux and all contaminants. Use of no clean flux is not acceptable." AssemblyNote 190,2380 r0 top
ZZ4 "These assemblies must comply with workmanship standards IPC-A-610 Class 2, unless otherwise specified." AssemblyNote 190,2260 r0 top
ZZ5 "These assemblies must comply with workmanship standards IPC-A-610 Class 2, unless otherwise specified." AssemblyNote 190,2140 r0 top
ZZ6 "These assemblies must comply with workmanship standards IPC-A-610 Class 2, unless otherwise specified." AssemblyNote 190,2030 r0 top

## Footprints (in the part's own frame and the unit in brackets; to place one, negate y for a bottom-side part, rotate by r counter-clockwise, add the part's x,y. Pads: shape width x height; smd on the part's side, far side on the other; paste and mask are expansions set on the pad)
0402L [mm] "0402 from SM-752 data"
  rect 0.6x0.5 smd: 1(-0.5,0) 2(0.5,0)
0603L [mm] "0603 from SM-752 data"
  rect 0.8x0.85 smd: 1(-0.7,0) 2(0.7,0)
  silkscreen extent -0.07,-0.32 0.07,0.32
0805L#1 [mm] "0805 from SM-752 data"
  rect 1.1x1.4 smd: 1(-0.75,0) 2(0.838,0)
0805L#2 [mm] "0805 from SM-752 data"
  rect 1.1x1.4 smd: 1(-0.75,0) 2(0.75,0)
AssemblyNote [mil] "Assembly Note"
AssemblyNoteLabel [mil] "Assembly Note for PCB Labels"
CE_Mark_5mm [mil] "Minimum text height for CE Mark"
FCC_disclaimer [mil]
Fiducial10-20 [mm]
  round 1 smd mask+0: 1(0,0)
  Top Layer keep-out circle w1.178: c0,0 r0.5
FP-CGA6P1X7S1A476M250AC_1210-MFG [mm]
  rrect9% 1.1x2.2 smd paste+0 mask+0: 1(-1.65,0) 2(1.65,0)
  silkscreen extent -0.72,-1.4 0.72,1.4
FP-CNA6P1X7R1H106K250AE_1210-MFG [mm]
  rrect9% 1.1x2.2 smd paste+0 mask+0: 1(-1.65,0) 2(1.65,0)
  silkscreen extent -0.72,-1.35 0.72,1.35
FP-EEE-FN1H680XL_RADIAL-MFG [mm]
  rrect6% 3.2x1.6 smd paste+0 mask+0: 1(-2.5,0) 2(2.5,0)
  silkscreen extent -4.8,-3.4 3.4,3.4
FP-XGL4020-102MEC_SMT_IND_4MM0_4MM0-MFG [mm]
  rrect10% 0.98x3.4 smd paste+0 mask+0: 1(-1.185,0) 2(1.185,0)
  silkscreen extent -2.72,-2.15 2.15,2.15
FP-XGL4030-761MEC_SMD_IND_4MM0_4MM0-MFG [mm]
  rrect10% 0.98x3.4 smd paste+0 mask+0: 1(-1.185,0) 2(1.185,0)
  silkscreen extent -2.15,-2.15 2.15,2.15
IEC_HotSurface_Small [mil]
  silkscreen extent -107,-93 107,92
Keystone_5019 [mm] "Test Point, Miniature, SMT"
  rect 3.8x2.03 smd: 1(0,0)
  silkscreen extent -2.31,-1.41 2.31,1.41
Label_650x200 [mil] "Thermal Transfer Label"
  round 1 on Mech13: 0(0,0)
  silkscreen extent -325,-100 325,100
MTG_159mil [mil] "159mil Non Plated Hole"
  round 150 hole 159 unplated: 1(0,0)
Phoenix_1729018 [mm] "Phoenix Contact"
  rect 1.905x1.905 hole 1.3: 1(-2.5,0)
  round 1.9 hole 1.3: 2(2.5,0)
  silkscreen extent -5.56,-4.08 5.01,4.07
RYF0022A-MFG [mm]
  round 0.278 smd paste+0 mask+0: 1(-1.28,1.53) 7(-1.28,-1.53) 12(1.28,-1.53) 18(1.28,1.53)
  rrect40% 0.75x0.25 smd paste+0 mask+0: 2(-1.575,1) 3(-1.575,0.5) 4(-1.575,0) 5(-1.575,-0.5) 6(-1.575,-1) 13(1.575,-1) 14(1.575,-0.5) 15(1.575,0) 16(1.575,0.5) 17(1.575,1)
  rrect40% 0.25x0.75 smd paste+0 mask+0: 8(-0.75,-1.825) 9(-0.25,-1.825) 10(0.25,-1.825) 11(0.75,-1.825) 19(0.75,1.825) 20(0.25,1.825) 21(-0.25,1.825) 22(-0.75,1.825)
  rrect6% 1.7x2.2 smd paste-1000 mask+0: 23(0,0)
  silkscreen extent -2.67,-2.6 1.8,2.6
SNT-100-BK-G [mil] "Samtec STEP model"
  round 1 on Mech3: 0(0,0)
TI_Stacked_Overlay_Small [mil]
TSW-110-07-G-S [mil] "Samtec 100mil, 1x10, 230 mil above insulator"
  rrect6% 64.96x64.96 hole 40: 1(-450,0)
  round 64.96 hole 40: 2(-350,0) 3(-250,0) 4(-150,0) 5(-50,0) 6(50,0) 7(150,0) 8(250,0) 9(350,0) 10(450,0)
  silkscreen extent -500,-50 500,50
WEEE_Minimum [mil] "WEEElie bin"
  silkscreen extent 22,-71 54,74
